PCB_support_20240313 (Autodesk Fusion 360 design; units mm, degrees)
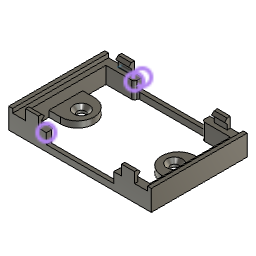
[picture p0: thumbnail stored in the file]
sketch "Esquisse1" plane through (0, 0, 0) normal (0, 0, 1) x axis (1, 0, 0)
  line L1 (-27.5, -18.5) -> (27.5, -18.5)
  line L2 (-27.5, 18.5) -> (-27.5, -18.5)
  line L3 (27.5, 18.5) -> (-27.5, 18.5)
  line L4 (27.5, -18.5) -> (27.5, 18.5)
  line L5 (-27.5, 18.5) -> (27.5, -18.5)
  line L6 (27.5, 18.5) -> (-27.5, -18.5)
  point P6 (0, 0)
  point P1 (0, 0)
  horizontal L1
  perpendicular L1 L2
  parallel L1 L3
  parallel L2 L4
  coincident L5 P6
  coincident L6 P6
  coincident P1 P6
  dimension "d3" = 6.4
  dimension "d3" = 6.4
  dimension "d1" distance = 55 (= "51 mm + 4 mm")
  dimension "d2" distance = 37 (= "34 mm + 3 mm")
extrude "Extrusion1" new body sketch "Esquisse1" profile of L1 L2 L3 L4 along normal blind 6.4
sketch "Esquisse2" plane through (0, 0, 6.4) normal (0, 0, 1) x axis (-1, 0, 0)
  line L1 (27.5, -18.5) -> (-27.5, -18.5)
  line L2 (27.5, 18.5) -> (27.5, -18.5)
  line L3 (-27.5, 18.5) -> (27.5, 18.5)
  line L4 (-27.5, -18.5) -> (-27.5, 18.5)
  line L5 (24, 15.5) -> (-24, 15.5)
  line L6 (24, -15.5) -> (24, 15.5)
  line L7 (-24, -15.5) -> (24, -15.5)
  line L8 (-24, 15.5) -> (-24, -15.5)
  line L9 (24, -15.5) -> (-24, 15.5)
  line L10 (-24, -15.5) -> (24, 15.5)
  point P10 (0, 0)
  point P1 (0, 0)
  point P8 (24, -15.5)
  point P9 (-24, -15.5)
  point P7 (24, 15.5)
  horizontal L5
  perpendicular L5 L6
  parallel L5 L7
  parallel L6 L8
  coincident L9 P10
  coincident L10 P10
  coincident P1 P10
  dimension "d5" distance P8 P9 = 48 (= "51 mm - 3 mm")
  dimension "d6" distance P7 P8 = 31 (= "34 mm - 3 mm")
extrude "Extrusion2" cut sketch "Esquisse2" profile of L5 L6 L7 L8 against normal blind 4
sketch "Esquisse3" plane through (0, 0, 6.4) normal (0, 0, 1) x axis (-1, 0, 0)
  line L1 (24, -15.5) -> (24, 15.5)
  line L2 (-24, -15.5) -> (24, -15.5)
  line L3 (-24, 15.5) -> (-24, -15.5)
  line L4 (24, 15.5) -> (-24, 15.5)
  line L5 (27.5, -18.5) -> (-27.5, -18.5)
  line L6 (27.5, 18.5) -> (27.5, -18.5)
  line L7 (-27.5, 18.5) -> (27.5, 18.5)
  line L8 (-27.5, -18.5) -> (-27.5, 18.5)
  line L9 (13, 18.5) -> (-13, 18.5)
  line L10 (13, -18.5) -> (13, 18.5)
  line L11 (-13, -18.5) -> (13, -18.5)
  line L12 (-13, 18.5) -> (-13, -18.5)
  line L13 (13, -18.5) -> (-13, 18.5)
  line L14 (-13, -18.5) -> (13, 18.5)
  point P14 (0, 0)
  point P1 (0, 0)
  point P12 (13, -18.5)
  point P13 (-13, -18.5)
  point P11 (13, 18.5)
  horizontal L9
  perpendicular L9 L10
  parallel L9 L11
  parallel L10 L12
  coincident L13 P14
  coincident L14 P14
  coincident P1 P14
  dimension "d9" distance P12 P13 = 26
  dimension "d10" distance P11 P12 = 37 (= "34 mm + 3 mm")
extrude "Extrusion3" cut sketch "Esquisse3" profile of L2 L4 L5 L7 L9 L10 L11 L12 against normal blind 4
sketch "Esquisse4" plane through (0, 0, 2.4) normal (0, 0, 1) x axis (-1, 0, 0)
  line L1 (24, -15.5) -> (13, -15.5)
  line L2 (24, 15.5) -> (24, -15.5)
  line L3 (13, 15.5) -> (24, 15.5)
  line L4 (-24, -15.5) -> (-24, 15.5)
  line L5 (13, 17) -> (-13, 17)
  line L6 (13, -17) -> (13, 17)
  line L7 (-13, -17) -> (13, -17)
  line L8 (-13, 17) -> (-13, -17)
  line L9 (13, -17) -> (-13, 17)
  line L10 (-13, -17) -> (13, 17)
  line L11 (24, -15.5) -> (13, -15.5)
  line L12 (24, -6.5) -> (24, -15.5)
  line L13 (13, -6.5) -> (24, -6.5)
  line L14 (13, -15.5) -> (13, -6.5)
  line L15 (24, 15.5) -> (13, 15.5)
  line L16 (24, 6.5) -> (24, 15.5)
  line L17 (13, 6.5) -> (24, 6.5)
  line L18 (13, 15.5) -> (13, 6.5)
  line L19 (-24, -15.5) -> (-13, -15.5)
  line L20 (-24, -6.5) -> (-24, -15.5)
  line L21 (-13, -6.5) -> (-24, -6.5)
  line L22 (-13, -15.5) -> (-13, -6.5)
  line L23 (-24, 15.5) -> (-13, 15.5)
  line L24 (-24, 6.5) -> (-24, 15.5)
  line L25 (-13, 6.5) -> (-24, 6.5)
  line L26 (-13, 15.5) -> (-13, 6.5)
  line L27 (13, 18.5) -> (13, 15.5)
  line L28 (-13, 18.5) -> (13, 18.5)
  line L29 (-13, 15.5) -> (-13, 18.5)
  line L30 (-24, 15.5) -> (-13, 15.5)
  line L31 (-13, -15.5) -> (-24, -15.5)
  line L32 (-13, -18.5) -> (-13, -15.5)
  line L33 (13, -18.5) -> (-13, -18.5)
  line L34 (13, -15.5) -> (13, -18.5)
  point P12 (0, 0)
  point P1 (0, 0)
  point P2 (13, -15.5)
  point P13 (13, -15.5)
  point P5 (13, 15.5)
  point P17 (13, 15.5)
  point P10 (13, -17)
  point P11 (-13, -17)
  point P9 (13, 17)
  point P14 (24, -15.5)
  point P16 (13, -6.5)
  point P18 (24, 15.5)
  point P20 (13, 6.5)
  point P21 (-13, -15.5)
  point P22 (-24, -15.5)
  point P24 (-13, -6.5)
  point P25 (-13, 15.5)
  point P26 (-24, 15.5)
  point P28 (-13, 6.5)
  horizontal L5
  perpendicular L5 L6
  parallel L5 L7
  parallel L6 L8
  coincident L9 P12
  coincident L10 P12
  coincident P1 P12
  horizontal L11
  vertical L12
  horizontal L13
  vertical L14
  coincident P2 P13
  horizontal L15
  vertical L16
  horizontal L17
  vertical L18
  coincident P5 P17
  horizontal L19
  vertical L20
  horizontal L21
  vertical L22
  horizontal L23
  vertical L24
  horizontal L25
  vertical L26
  dimension "d13" distance P10 P11 = 26
  dimension "d14" distance P9 P10 = 34
  dimension "d58" distance P13 P14 = 11
  dimension "d59" distance P13 P16 = 9
  dimension "d60" distance P17 P18 = 11
  dimension "d61" distance P17 P20 = 9
  dimension "d62" distance P21 P22 = 11
  dimension "d63" distance P21 P24 = 9
  dimension "d64" distance P25 P26 = 11
  dimension "d65" distance P25 P28 = 9
extrude "Extrusion4" cut sketch "Esquisse4" profile of L1 L2 L3 L4 L5 L6 L7 L8 L11 L12 L13 L14 L15 L16 L17 L18 L19 L20 L21 L22 L23 L24 L25 L26 no distance stored
sketch "Esquisse5" plane through (0, 0, 6.4) normal (0, 0, 1) x axis (-1, 0, 0)
  line L1 (24, 15.5) -> (13, 15.5)
  line L2 (24, -15.5) -> (24, 15.5)
  line L3 (13, -15.5) -> (24, -15.5)
  line L4 (27.5, -18.5) -> (13, -18.5)
  line L5 (27.5, 18.5) -> (27.5, -18.5)
  line L6 (13, 18.5) -> (27.5, 18.5)
  line L7 (26, -18.5) -> (27.5, -18.5)
  line L8 (26, 18.5) -> (26, -18.5)
  line L9 (27.5, 18.5) -> (26, 18.5)
  line L10 (27.5, -18.5) -> (27.5, 18.5)
  line L11 (-30, -18.5) -> (27.5, -18.5)
  line L12 (-26, -18.5) -> (-27.5, -18.5)
  line L13 (-26, 18.5) -> (-26, -18.5)
  line L14 (-27.5, 18.5) -> (-26, 18.5)
  line L15 (-27.5, -18.5) -> (-27.5, 18.5)
  line L16 (13, 15.5) -> (13, 18.5)
  line L17 (13, -18.5) -> (13, -15.5)
  point P8 (27.5, -18.5)
  point P10 (27.5, -18.5)
  point P15 (-27.5, -18.5)
  point P16 (-26, -18.5)
  point P18 (-27.5, 18.5)
  point P12 (26, 18.5)
  point P17 (-26, 18.5)
  horizontal L7
  vertical L8
  horizontal L9
  vertical L10
  coincident P8 P10
  perpendicular L10 L11
  horizontal L12
  vertical L13
  horizontal L14
  vertical L15
  coincident L11 P15
  dimension "d3" = 6.4
  dimension "d3" = 6.4
  dimension "d23" distance P15 P16 = 1.5
  dimension "d24" distance P15 P18 = 37
  dimension "d25" distance P12 P17 = 52
  dimension "d16" distance = 1.5
  dimension "d17" distance = 37
extrude "Extrusion5" add sketch "Esquisse5" profile of L4 L5 L6 L7 L8 L9 L10 L12 L13 L14 L15 along normal blind 1.6
work_plane "Plan de construction" AlongDistance 6.4
sketch "Esquisse6" plane through (0, 0, 6.4) normal (0, 0, 1) x axis (1, 0, 0)
  line L1 (-16, 18.5) -> (-21, 18.5)
  line L2 (-16, 17.25) -> (-16, 18.5)
  line L3 (-21, 17.25) -> (-16, 17.25)
  line L4 (-21, 18.5) -> (-21, 17.25)
  point P2 (-21, 18.5)
  point P3 (-16, 18.5)
  point P5 (-21, 17.25)
  point P4 (-16, 17.25)
  point P6 (-13, 15.5)
  horizontal L1
  vertical L2
  horizontal L3
  vertical L4
  dimension "d27" distance P2 P3 = 5
  dimension "d28" distance P2 P5 = 1.25
  dimension "d72" distance P4 P6 = 1.75
extrude "Extrusion6" add sketch "Esquisse6" along normal blind 4
sketch "Esquisse7" plane through (0, 17.25, 0) normal (0, -1, 0) x axis (1, 0, 0)
  line L1 (-16, 10.4) -> (-16, 6.4)
  line L2 (-21, 10.4) -> (-16, 10.4)
  line L3 (-21, 6.4) -> (-21, 10.4)
  line L4 (-16, 10.4) -> (-21, 10.4)
  line L5 (-16, 8.4) -> (-16, 10.4)
  line L6 (-21, 8.4) -> (-16, 8.4)
  line L7 (-21, 10.4) -> (-21, 8.4)
  line L8 (-16, 6.4) -> (-21, 6.4)
  point P8 (-16, 8.4)
  point P5 (-21, 10.4)
  point P6 (-21, 10.4)
  horizontal L4
  vertical L5
  horizontal L6
  vertical L7
  midpoint L1 P8
  coincident P5 P6
extrude "Extrusion7" add sketch "Esquisse7" profile of L1 L2 L3 L4 L5 L6 L7 along normal blind 1
chamfer "Chanfrein" distance 1
mirror "Symétrie miroir1" mirrorStitchTolerance 0.1
mirror "Symétrie miroir2" mirrorStitchTolerance 0.1
sketch "Esquisse8" plane through (0, 0, 2.4) normal (0, 0, 1) x axis (-1, 0, 0)
  line L1 (13, -6.5) -> (13, 6.5)
  line L2 (24, 6.5) -> (24, -6.5)
  line L3 (24, -6.5) -> (13, -6.5)
  line L4 (13, 6.5) -> (24, 6.5)
  circle C1 centre (18, 0) radius 1.5
  circle C2 centre (-18, 0) radius 1.5
  point P6 (18, 0)
  point P8 (0, 0)
  point P7 (-18, 0)
  dimension "d48" diameter C1 = 3
  dimension "d49" diameter C2 = 3
  dimension "d50" distance P6 P8 = 18
  dimension "d51" distance P7 P8 = 18
hole "Perçage" HoleDiameter 3.2 TipAngle 118 CSDiameter 6 CSAngle 90
fillet "Congé2" radius 6.5
fillet "Congé3" radius 1 0.5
